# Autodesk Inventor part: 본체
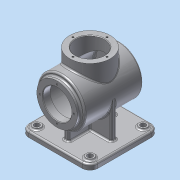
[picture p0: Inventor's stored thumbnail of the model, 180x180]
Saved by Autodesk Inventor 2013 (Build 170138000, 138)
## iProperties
Created: 2015-07
Part Number: 본체
Material: 알루미늄 6061
Document SubType Name: Modeling
Designer: dgall
Density: 2.71 g/cm^3
Mass: 1277.63 g
Surface Area: 1267.91 cm^2
Volume: 471.449 cm^3
Author: dgall
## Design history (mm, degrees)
sketch "스케치1"
  geometry: L1 (-65, 65)-(65, 65); L2 (65, 65)-(65, -65); L3 (65, -65)-(-65, -65); L4 (-65, -65)-(-65, 65); 3 further points
  constraints: 8 end point, 2 midpoint, 2 parallel, 1 horizontal, 1 horizontal alignment, 1 perpendicular, 1 vertical alignment
  dimensions: "d0" = 130 distance of L1.start L1.end; "d2" = 130 distance of L3.end L1.start
extrude "돌출1" new body sketch "스케치1" distance "d3" = 10; taper "d4" = 0 deg
sketch "스케치2"
  geometry: L1 (65, 0)-(-65, 0) reference; L2 (65, -10)-(-65, -10) reference; C1 r 45 at (0, 68); 2 further points
  constraints: 1 centre point, 1 midpoint, 1 vertical alignment
  dimensions: "d5" = 90 diameter of C1; "d7" = 78 distance from line of L2 C1.centre
extrude "돌출2" join sketch "스케치2" stored distance "d8" = 110; taper "d9" = 0 deg
sketch "스케치3"
  geometry: C1 r 45 at (0, 0) reference; C2 r 38 at (0, 0); 1 further point
  constraints: 1 centre point, 1 coincident
  dimensions: "d10" = 76 diameter of C2
extrude "돌출3" join sketch "스케치3" distance "d12" = 7; taper "d13" = 0 deg
sketch "스케치4"
  geometry: L1 (-65, 65)-(65, 65) reference; L2 (-65, -65)-(-65, 65) reference; C1 r 7.5 at (-50, 50); 1 further point
  constraints: 1 centre point
  dimensions: "d14" = 15 diameter of C1; "d17" = 15 distance from line of L2 C1.centre; "d18" = 15 distance from line of L1 C1.centre (= d17)
extrude "돌출4" join sketch "스케치4" distance "d19" = 3; taper "d20" = 0 deg
node "작업 평면1"
sketch "스케치5"
  geometry: C1 r 38 at (0, 0); 1 further point
  constraints: 1 centre point, 1 coincident
  dimensions: "d28" = 76 diameter of C1
extrude "돌출5" join sketch "스케치5" stored distance "d30" = 20; taper "d31" = 0 deg
sketch "스케치6"
  geometry: L1 (-5, 45)-(5, 45); L2 (5, -45)-(-5, -45); L3 (45, 5)-(45, -5); L4 (-45, -5)-(-45, 5); L5 (5, 45)-(5, 5); L6 (5, -5)-(5, -45); L7 (-5, -45)-(-5, -5); L8 (-5, 5)-(-5, 45); L9 (45, -5)-(5, -5); L10 (-5, -5)-(-45, -5); L11 (-45, 5)-(-5, 5); L12 (5, 5)-(45, 5); 5 further points
  constraints: 24 end point, 10 parallel, 4 horizontal alignment, 4 perpendicular, 4 vertical alignment, 3 horizontal, 2 midpoint
  dimensions: "d32" = 90 distance of L1.end L2.start; "d34" = 90 distance of L4.end L3.start; "d35" = 10 distance of L1.start L1.end; "d36" = 10 distance of L3.start L3.end; "d37" = 45 distance of point (-45, 0) point (0, 0); "d38" = 45 distance of point (0, 0) point (0, 45)
extrude "돌출6" join sketch "스케치6" stored distance "d39" = 20; taper "d40" = 0 deg
hole "구멍1" diameter "d43" = 54; stored, may be unused: countersink angle "d47" = 90 deg, drill point angle "d49" = 0 deg; dims "d41" = 10, "d42" = 10, "d44" = 6, "d45" = 4, "d46" = 2, "d48" = 14
hole "구멍2" diameter "d52" = 80; stored, may be unused: countersink angle "d56" = 90 deg, drill point angle "d58" = 0 deg; dims "d50" = 10, "d51" = 10, "d53" = 6, "d54" = 4, "d55" = 2, "d57" = 96
hole "구멍3" diameter "d61" = 54; stored, may be unused: countersink angle "d65" = 90 deg, drill point angle "d67" = 0 deg; dims "d59" = 10, "d60" = 10, "d62" = 6, "d63" = 4, "d64" = 2, "d66" = 96
sketch "스케치7"
  geometry: C1 r 27 at (0, 0) reference; 1 further point
  constraints: 1 vertical alignment
  dimensions: "d68" = 32 distance of point (0, 32) C1.centre
hole "구멍4" sketch "스케치7" at (0, 32) diameter "d69" = 3.242; stored, may be unused: countersink angle "d73" = 90 deg, drill point angle "d75" = 118 deg; dims "d70" = 8, "d71" = 4, "d72" = 2, "d74" = 10
sketch "스케치8"
  geometry: C1 r 27 at (0, 0) reference; 2 further points
  constraints: 1 vertical alignment
  dimensions: "d79" = 32 distance of point (0, 32) C1.centre
hole "구멍5" sketch "스케치8" at (0, 32) diameter "d80" = 3.242; stored, may be unused: countersink angle "d84" = 90 deg, drill point angle "d86" = 118 deg; dims "d81" = 8, "d82" = 4, "d83" = 2, "d85" = 10
sketch "스케치9"
  geometry: C1 r 45 at (0, 0) reference; 2 further points
  constraints: 1 coincident, 1 other
feature "엠보싱1" sketch "스케치9" dims "d0" = 130, "d2" = 130, "d12" = 7, "d90" = 0.5, "d91" = 0
hole "구멍6" diameter "d94" = 10; stored, may be unused: countersink angle "d98" = 90 deg, drill point angle "d100" = 118 deg; dims "d92" = 10, "d93" = 10, "d95" = 8, "d96" = 4, "d97" = 2, "d99" = 10
fillet "모깎기1" dims "d107" = 3
chamfer "모따기1" distance "d114" = 1; stored, may be unused: second distance "d115" = 2, angle "d116" = 45 deg
fillet "모깎기2" dims "d117" = 3
fillet "모깎기3" dims "d118" = 3
fillet "모깎기4" dims "d119" = 3
fillet "모깎기5" dims "d120" = 3
fillet "모깎기6" dims "d121" = 15
fillet "모깎기7" dims "d122" = 3
node "솔리드1"
pattern_linear "직사각형 패턴1" dims "d23" = 100
pattern_circular "원형 패턴1" dims angle "d77" = 360 deg
pattern_circular "원형 패턴2" dims angle "d88" = 360 deg
pattern_linear "직사각형 패턴2" dims "d103" = 100
pattern_linear "직사각형 패턴3" dims "d110" = 100
